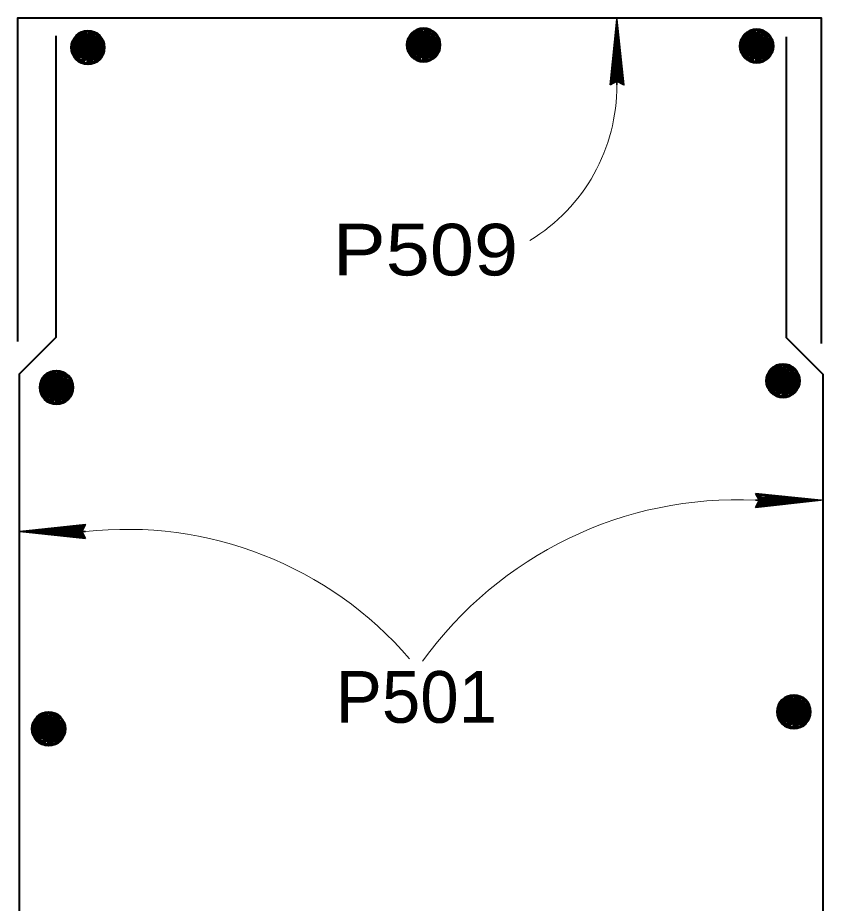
# Model space of a CAD drawing. Extents: x 6.34 to 9.53, y -1.46 to 0.53.
# Drawn here: x 7.8124 to 7.9424, y -0.5501 to -0.4073 of the extents above; entities that cross this region are included whole.
import ezdxf

# ---------------------------------------------------------------- set-up
doc = ezdxf.new("R2010")
doc.units = 0
doc.header["$LTSCALE"] = 0.0033
doc.layers.add('1', color=7, linetype='Continuous', lineweight=40)

msp = doc.modelspace()

# ---------------------------------------------------------------- linework, layer by layer
at = {"layer": '1', "lineweight": 35}
for p, q in [((7.909083, -0.418083), (7.909083, -0.4075)), ((7.908083, -0.417833), (7.909, -0.41)), ((7.908083, -0.417833), (7.909, -0.41)), ((7.908167, -0.417833), (7.909, -0.41)), ((7.90825, -0.417833), (7.909083, -0.41)), ((7.90825, -0.417833), (7.90925, -0.41)), ((7.90975, -0.417917), (7.909, -0.410583)), ((7.909917, -0.417833), (7.909083, -0.4105)), ((7.91, -0.417833), (7.90925, -0.4105)), ((7.910167, -0.417833), (7.909333, -0.4105)), ((7.93175, -0.484083), (7.939583, -0.485)), ((7.93175, -0.484083), (7.939583, -0.485)), ((7.93175, -0.484167), (7.939583, -0.485)), ((7.93175, -0.48425), (7.939583, -0.485083)), ((7.93175, -0.48425), (7.939583, -0.48525)), ((7.9315, -0.485083), (7.942083, -0.485083)), ((7.931667, -0.48575), (7.939, -0.485)), ((7.93175, -0.485917), (7.939083, -0.485083)), ((7.93175, -0.486), (7.939083, -0.48525)), ((7.93175, -0.486167), (7.939083, -0.485333)), ((7.823083, -0.491), (7.81525, -0.49)), ((7.823083, -0.489083), (7.81575, -0.489917)), ((7.823083, -0.48925), (7.81575, -0.49)), ((7.823083, -0.489333), (7.81575, -0.490167)), ((7.823167, -0.4895), (7.815833, -0.49025)), ((7.823333, -0.490167), (7.81275, -0.490167)), ((7.823083, -0.491), (7.81525, -0.490167)), ((7.823083, -0.491167), (7.81525, -0.49025)), ((7.823083, -0.491167), (7.81525, -0.49025)), ((7.823083, -0.491083), (7.81525, -0.49025))]:
    msp.add_line(p, q, dxfattribs=at)
at = {"layer": '1'}
for p, q in [((7.824, -0.411), (7.825333, -0.41)), ((7.826083, -0.410833), (7.824833, -0.409667)), ((7.87625, -0.40975), (7.880083, -0.410417)), ((7.878167, -0.410583), (7.8795, -0.409583)), ((7.88025, -0.410417), (7.879, -0.40925)), ((7.93, -0.409917), (7.933833, -0.410583)), ((7.931917, -0.41075), (7.93325, -0.40975)), ((7.934, -0.410583), (7.93275, -0.409417)), ((7.821667, -0.4105), (7.82625, -0.412667)), ((7.821917, -0.410917), (7.825833, -0.411667)), ((7.821917, -0.411083), (7.825833, -0.411833)), ((7.821917, -0.411333), (7.82575, -0.412083)), ((7.822, -0.4105), (7.825917, -0.411167)), ((7.822, -0.410667), (7.825917, -0.411417)), ((7.822083, -0.410167), (7.825917, -0.410833)), ((7.875833, -0.410083), (7.880417, -0.41225)), ((7.876, -0.411083), (7.879833, -0.41175)), ((7.876, -0.41125), (7.879833, -0.412)), ((7.876083, -0.4105), (7.88, -0.41125)), ((7.876083, -0.410667), (7.88, -0.411417)), ((7.876083, -0.410917), (7.879917, -0.411667)), ((7.876167, -0.410083), (7.880083, -0.41075)), ((7.876167, -0.41025), (7.880083, -0.411)), ((7.929583, -0.41025), (7.934167, -0.412417)), ((7.92975, -0.41125), (7.933583, -0.411917)), ((7.92975, -0.411417), (7.933583, -0.412167)), ((7.929833, -0.410667), (7.93375, -0.411417)), ((7.929833, -0.410833), (7.93375, -0.411583)), ((7.929833, -0.411083), (7.933667, -0.411833)), ((7.929917, -0.41025), (7.933833, -0.410917)), ((7.929917, -0.410417), (7.933833, -0.411167)), ((7.821583, -0.41275), (7.8255, -0.4135)), ((7.821667, -0.412333), (7.825583, -0.413083)), ((7.82175, -0.411917), (7.825583, -0.412667)), ((7.82175, -0.412083), (7.825583, -0.412833)), ((7.821833, -0.4115), (7.825667, -0.412167)), ((7.821833, -0.411667), (7.825667, -0.412417)), ((7.875667, -0.412833), (7.8795, -0.413583)), ((7.87575, -0.412333), (7.879667, -0.413083)), ((7.87575, -0.4125), (7.879583, -0.41325)), ((7.87575, -0.41275), (7.879583, -0.413417)), ((7.875833, -0.411917), (7.87975, -0.412667)), ((7.875917, -0.4115), (7.87975, -0.41225)), ((7.875917, -0.411667), (7.87975, -0.412417)), ((7.9295, -0.4125), (7.933417, -0.41325)), ((7.9295, -0.412667), (7.933333, -0.413417)), ((7.929583, -0.412083), (7.9335, -0.412833)), ((7.929667, -0.411667), (7.9335, -0.412417)), ((7.929667, -0.411833), (7.9335, -0.412583)), ((7.8215, -0.41325), (7.825333, -0.414)), ((7.8215, -0.413417), (7.825333, -0.414167)), ((7.821583, -0.412917), (7.825417, -0.413667)), ((7.821583, -0.413167), (7.825417, -0.413833)), ((7.825833, -0.413667), (7.822083, -0.414083)), ((7.875667, -0.413), (7.8795, -0.41375)), ((7.88, -0.41325), (7.87625, -0.413667)), ((7.929417, -0.413), (7.93325, -0.41375)), ((7.929417, -0.413167), (7.93325, -0.413917)), ((7.9295, -0.412917), (7.933333, -0.413583)), ((7.93375, -0.413417), (7.93, -0.413833)), ((7.933833, -0.46425), (7.938417, -0.466417)), ((7.934167, -0.46425), (7.938083, -0.464917)), ((7.93425, -0.463917), (7.938083, -0.464583)), ((7.936167, -0.46475), (7.9375, -0.46375)), ((7.93825, -0.464583), (7.937, -0.463417)), ((7.816583, -0.465333), (7.821167, -0.4675)), ((7.816833, -0.46575), (7.82075, -0.4665)), ((7.816917, -0.465333), (7.820833, -0.466)), ((7.816917, -0.4655), (7.820833, -0.46625)), ((7.817, -0.465), (7.820833, -0.465667)), ((7.818917, -0.465833), (7.82025, -0.464833)), ((7.821, -0.465667), (7.81975, -0.4645)), ((7.933917, -0.465667), (7.93775, -0.466417)), ((7.934, -0.46525), (7.937833, -0.465917)), ((7.934, -0.465417), (7.937833, -0.466167)), ((7.934083, -0.464667), (7.938, -0.465417)), ((7.934083, -0.464833), (7.938, -0.465583)), ((7.934083, -0.465083), (7.937917, -0.465833)), ((7.934167, -0.464417), (7.938083, -0.465167)), ((7.816583, -0.467167), (7.8205, -0.467917)), ((7.816667, -0.46675), (7.8205, -0.4675)), ((7.816667, -0.466917), (7.8205, -0.467667)), ((7.81675, -0.466333), (7.820583, -0.467)), ((7.81675, -0.4665), (7.820583, -0.46725)), ((7.816833, -0.465917), (7.82075, -0.466667)), ((7.816833, -0.466167), (7.820667, -0.466917)), ((7.933667, -0.467), (7.9375, -0.46775)), ((7.933667, -0.467167), (7.9375, -0.467917)), ((7.93375, -0.4665), (7.937667, -0.46725)), ((7.93375, -0.466667), (7.937583, -0.467417)), ((7.93375, -0.466917), (7.937583, -0.467583)), ((7.933833, -0.466083), (7.93775, -0.466833)), ((7.933917, -0.465833), (7.93775, -0.466583)), ((7.816417, -0.468083), (7.82025, -0.468833)), ((7.816417, -0.46825), (7.82025, -0.469)), ((7.8165, -0.467583), (7.820417, -0.468333)), ((7.8165, -0.46775), (7.820333, -0.4685)), ((7.8165, -0.468), (7.820333, -0.468667)), ((7.82075, -0.4685), (7.817, -0.468917)), ((7.938, -0.467417), (7.93425, -0.467833)), ((7.937917, -0.518167), (7.93925, -0.517167)), ((7.94, -0.518), (7.93875, -0.516833)), ((7.935583, -0.517667), (7.940167, -0.519833)), ((7.935833, -0.518083), (7.93975, -0.518833)), ((7.935833, -0.51825), (7.93975, -0.519)), ((7.935833, -0.5185), (7.939667, -0.51925)), ((7.935917, -0.517667), (7.939833, -0.518333)), ((7.935917, -0.517833), (7.939833, -0.518583)), ((7.936, -0.517333), (7.939833, -0.518)), ((7.817667, -0.520917), (7.819, -0.519917)), ((7.81975, -0.52075), (7.8185, -0.519583)), ((7.9355, -0.519917), (7.939417, -0.520667)), ((7.935583, -0.5195), (7.9395, -0.52025)), ((7.935667, -0.519083), (7.9395, -0.519833)), ((7.935667, -0.51925), (7.9395, -0.52)), ((7.93575, -0.518667), (7.939583, -0.519333)), ((7.93575, -0.518833), (7.939583, -0.519583)), ((7.815333, -0.520417), (7.819917, -0.522583)), ((7.8155, -0.521417), (7.819333, -0.522083)), ((7.815583, -0.520833), (7.8195, -0.521583)), ((7.815583, -0.521), (7.8195, -0.52175)), ((7.815583, -0.52125), (7.819417, -0.522)), ((7.815667, -0.520417), (7.819583, -0.521083)), ((7.815667, -0.520583), (7.819583, -0.521333)), ((7.81575, -0.520083), (7.819583, -0.52075)), ((7.935417, -0.520417), (7.93925, -0.521167)), ((7.935417, -0.520583), (7.93925, -0.521333)), ((7.9355, -0.520083), (7.939333, -0.520833)), ((7.9355, -0.520333), (7.939333, -0.521)), ((7.93975, -0.520833), (7.936, -0.52125)), ((7.81525, -0.522667), (7.819167, -0.523417)), ((7.81525, -0.522833), (7.819083, -0.523583)), ((7.815333, -0.52225), (7.81925, -0.523)), ((7.815417, -0.521833), (7.81925, -0.522583)), ((7.815417, -0.522), (7.81925, -0.52275)), ((7.8155, -0.521583), (7.819333, -0.522333)), ((7.815167, -0.523167), (7.819, -0.523917)), ((7.815167, -0.523333), (7.819, -0.524083)), ((7.81525, -0.523083), (7.819083, -0.52375)), ((7.8195, -0.523583), (7.81575, -0.524))]:
    msp.add_line(p, q, dxfattribs=at)
at = {"layer": '1', "lineweight": 60}
for p, q in [((7.821917, -0.4105), (7.82175, -0.413417)), ((7.822167, -0.4105), (7.821917, -0.413417)), ((7.822333, -0.4105), (7.822167, -0.4135)), ((7.8225, -0.4105), (7.82225, -0.4135)), ((7.822667, -0.4105), (7.8225, -0.4135)), ((7.822917, -0.4105), (7.82275, -0.4135)), ((7.823167, -0.4105), (7.822917, -0.4135)), ((7.82325, -0.410583), (7.823083, -0.4135)), ((7.823417, -0.410583), (7.82325, -0.4135)), ((7.823583, -0.410583), (7.823417, -0.4135)), ((7.823833, -0.410583), (7.823583, -0.4135)), ((7.824, -0.410583), (7.823833, -0.4135)), ((7.82425, -0.410667), (7.824, -0.413583)), ((7.8245, -0.410667), (7.82425, -0.413583)), ((7.824667, -0.410667), (7.8245, -0.413583)), ((7.82475, -0.410667), (7.824583, -0.413583)), ((7.824917, -0.410667), (7.82475, -0.413583)), ((7.825, -0.410667), (7.824833, -0.413583)), ((7.82525, -0.41075), (7.825, -0.413667)), ((7.825417, -0.41075), (7.82525, -0.413667)), ((7.825583, -0.41075), (7.825333, -0.413667)), ((7.82575, -0.41075), (7.825583, -0.413667)), ((7.826, -0.41075), (7.825833, -0.413667)), ((7.82625, -0.412667), (7.826083, -0.410833)), ((7.876083, -0.410083), (7.875917, -0.413)), ((7.876333, -0.410083), (7.876083, -0.413)), ((7.8765, -0.410083), (7.876333, -0.413083)), ((7.876667, -0.410083), (7.876417, -0.413083)), ((7.876833, -0.410083), (7.876667, -0.413083)), ((7.877083, -0.410083), (7.876917, -0.413083)), ((7.877333, -0.410083), (7.877083, -0.413083)), ((7.877417, -0.410167), (7.87725, -0.413083)), ((7.877583, -0.410167), (7.877417, -0.413083)), ((7.87775, -0.410167), (7.877583, -0.413083)), ((7.878, -0.410167), (7.87775, -0.413083)), ((7.878167, -0.410167), (7.878, -0.413083)), ((7.878417, -0.41025), (7.878167, -0.413167)), ((7.878667, -0.41025), (7.878417, -0.413167)), ((7.878833, -0.41025), (7.878667, -0.413167)), ((7.878917, -0.41025), (7.87875, -0.413167)), ((7.879083, -0.41025), (7.878917, -0.413167)), ((7.879167, -0.41025), (7.879, -0.413167)), ((7.879417, -0.410333), (7.879167, -0.41325)), ((7.879583, -0.410333), (7.879417, -0.41325)), ((7.87975, -0.410333), (7.8795, -0.41325)), ((7.879917, -0.410333), (7.87975, -0.41325)), ((7.880167, -0.410333), (7.88, -0.41325)), ((7.880417, -0.41225), (7.88025, -0.410417)), ((7.929833, -0.41025), (7.929667, -0.413167)), ((7.930083, -0.41025), (7.929833, -0.413167)), ((7.93025, -0.41025), (7.930083, -0.41325)), ((7.930417, -0.41025), (7.930167, -0.41325)), ((7.930583, -0.41025), (7.930417, -0.41325)), ((7.930833, -0.41025), (7.930667, -0.41325)), ((7.931083, -0.41025), (7.930833, -0.41325)), ((7.931167, -0.410333), (7.931, -0.41325)), ((7.931333, -0.410333), (7.931167, -0.41325)), ((7.9315, -0.410333), (7.931333, -0.41325)), ((7.93175, -0.410333), (7.9315, -0.41325)), ((7.931917, -0.410333), (7.93175, -0.41325)), ((7.932167, -0.410417), (7.931917, -0.413333)), ((7.932417, -0.410417), (7.932167, -0.413333)), ((7.932583, -0.410417), (7.932417, -0.413333)), ((7.932667, -0.410417), (7.9325, -0.413333)), ((7.932833, -0.410417), (7.932667, -0.413333)), ((7.932917, -0.410417), (7.93275, -0.413333)), ((7.933167, -0.4105), (7.932917, -0.413417)), ((7.933333, -0.4105), (7.933167, -0.413417)), ((7.9335, -0.4105), (7.93325, -0.413417)), ((7.933667, -0.4105), (7.9335, -0.413417)), ((7.933917, -0.4105), (7.93375, -0.413417)), ((7.934167, -0.412417), (7.934, -0.410583)), ((7.82625, -0.412667), (7.8215, -0.413417)), ((7.880417, -0.41225), (7.875667, -0.413)), ((7.934167, -0.412417), (7.929417, -0.413167)), ((7.934083, -0.46425), (7.933917, -0.467167)), ((7.934333, -0.46425), (7.934083, -0.467167)), ((7.9345, -0.46425), (7.934333, -0.46725)), ((7.934667, -0.46425), (7.934417, -0.46725)), ((7.934833, -0.46425), (7.934667, -0.46725)), ((7.935083, -0.46425), (7.934917, -0.46725)), ((7.935333, -0.46425), (7.935083, -0.46725)), ((7.935417, -0.464333), (7.93525, -0.46725)), ((7.935583, -0.464333), (7.935417, -0.46725)), ((7.93575, -0.464333), (7.935583, -0.46725)), ((7.936, -0.464333), (7.93575, -0.46725)), ((7.936167, -0.464333), (7.936, -0.46725)), ((7.816833, -0.465333), (7.816667, -0.46825)), ((7.817083, -0.465333), (7.816833, -0.46825)), ((7.81725, -0.465333), (7.817083, -0.468333)), ((7.817417, -0.465333), (7.817167, -0.468333)), ((7.817583, -0.465333), (7.817417, -0.468333)), ((7.817833, -0.465333), (7.817667, -0.468333)), ((7.818083, -0.465333), (7.817833, -0.468333)), ((7.818167, -0.465417), (7.818, -0.468333)), ((7.818333, -0.465417), (7.818167, -0.468333)), ((7.8185, -0.465417), (7.818333, -0.468333)), ((7.81875, -0.465417), (7.8185, -0.468333)), ((7.818917, -0.465417), (7.81875, -0.468333)), ((7.819167, -0.4655), (7.818917, -0.468417)), ((7.819417, -0.4655), (7.819167, -0.468417)), ((7.819583, -0.4655), (7.819417, -0.468417)), ((7.819667, -0.4655), (7.8195, -0.468417)), ((7.819833, -0.4655), (7.819667, -0.468417)), ((7.819917, -0.4655), (7.81975, -0.468417)), ((7.820167, -0.465583), (7.819917, -0.4685)), ((7.820333, -0.465583), (7.820167, -0.4685)), ((7.8205, -0.465583), (7.82025, -0.4685)), ((7.820667, -0.465583), (7.8205, -0.4685)), ((7.820917, -0.465583), (7.82075, -0.4685)), ((7.821167, -0.4675), (7.821, -0.465667)), ((7.936417, -0.464417), (7.936167, -0.467333)), ((7.936667, -0.464417), (7.936417, -0.467333)), ((7.936833, -0.464417), (7.936667, -0.467333)), ((7.936917, -0.464417), (7.93675, -0.467333)), ((7.937083, -0.464417), (7.936917, -0.467333)), ((7.937167, -0.464417), (7.937, -0.467333)), ((7.937417, -0.4645), (7.937167, -0.467417)), ((7.937583, -0.4645), (7.937417, -0.467417)), ((7.93775, -0.4645), (7.9375, -0.467417)), ((7.937917, -0.4645), (7.93775, -0.467417)), ((7.938167, -0.4645), (7.938, -0.467417)), ((7.938417, -0.466417), (7.93825, -0.464583)), ((7.938417, -0.466417), (7.933667, -0.467167)), ((7.821167, -0.4675), (7.816417, -0.46825)), ((7.935833, -0.517667), (7.935667, -0.520583)), ((7.936083, -0.517667), (7.935833, -0.520583)), ((7.93625, -0.517667), (7.936083, -0.520667)), ((7.936417, -0.517667), (7.936167, -0.520667)), ((7.936583, -0.517667), (7.936417, -0.520667)), ((7.936833, -0.517667), (7.936667, -0.520667)), ((7.937083, -0.517667), (7.936833, -0.520667)), ((7.937167, -0.51775), (7.937, -0.520667)), ((7.937333, -0.51775), (7.937167, -0.520667)), ((7.9375, -0.51775), (7.937333, -0.520667)), ((7.93775, -0.51775), (7.9375, -0.520667)), ((7.937917, -0.51775), (7.93775, -0.520667)), ((7.938167, -0.517833), (7.937917, -0.52075)), ((7.938417, -0.517833), (7.938167, -0.52075)), ((7.938583, -0.517833), (7.938417, -0.52075)), ((7.938667, -0.517833), (7.9385, -0.52075)), ((7.938833, -0.517833), (7.938667, -0.52075)), ((7.938917, -0.517833), (7.93875, -0.52075)), ((7.939167, -0.517917), (7.938917, -0.520833)), ((7.939333, -0.517917), (7.939167, -0.520833)), ((7.9395, -0.517917), (7.93925, -0.520833)), ((7.939667, -0.517917), (7.9395, -0.520833)), ((7.939917, -0.517917), (7.93975, -0.520833)), ((7.940167, -0.519833), (7.94, -0.518)), ((7.940167, -0.519833), (7.935417, -0.520583)), ((7.815583, -0.520417), (7.815417, -0.523333)), ((7.815833, -0.520417), (7.815583, -0.523333)), ((7.816, -0.520417), (7.815833, -0.523417)), ((7.816167, -0.520417), (7.815917, -0.523417)), ((7.816333, -0.520417), (7.816167, -0.523417)), ((7.816583, -0.520417), (7.816417, -0.523417)), ((7.816833, -0.520417), (7.816583, -0.523417)), ((7.816917, -0.5205), (7.81675, -0.523417)), ((7.817083, -0.5205), (7.816917, -0.523417)), ((7.81725, -0.5205), (7.817083, -0.523417)), ((7.8175, -0.5205), (7.81725, -0.523417)), ((7.817667, -0.5205), (7.8175, -0.523417)), ((7.817917, -0.520583), (7.817667, -0.5235)), ((7.818167, -0.520583), (7.817917, -0.5235)), ((7.818333, -0.520583), (7.818167, -0.5235)), ((7.818417, -0.520583), (7.81825, -0.5235)), ((7.818583, -0.520583), (7.818417, -0.5235)), ((7.818667, -0.520583), (7.8185, -0.5235)), ((7.818917, -0.520667), (7.818667, -0.523583)), ((7.819083, -0.520667), (7.818917, -0.523583)), ((7.81925, -0.520667), (7.819, -0.523583)), ((7.819417, -0.520667), (7.81925, -0.523583)), ((7.819667, -0.520667), (7.8195, -0.523583)), ((7.819917, -0.522583), (7.81975, -0.52075)), ((7.819917, -0.522583), (7.815167, -0.523333))]:
    msp.add_line(p, q, dxfattribs=at)
at = {"layer": '1'}
for points in [[(7.812417, -0.4595), (7.812417, -0.40725), (7.942083, -0.40725), (7.942083, -0.459833)], [(7.818583, -0.410167), (7.818583, -0.458833), (7.812667, -0.46475), (7.812667, -0.673083), (7.818583, -0.679), (7.818583, -0.711417)], [(7.9365, -0.708167), (7.9365, -0.679083), (7.942417, -0.673167), (7.942417, -0.464833), (7.9365, -0.458917), (7.9365, -0.410333)], [(7.8215, -0.413417), (7.823583, -0.414667), (7.825333, -0.414167), (7.82625, -0.412667)], [(7.875667, -0.413), (7.87775, -0.41425), (7.8795, -0.41375), (7.880417, -0.41225)], [(7.929417, -0.413167), (7.9315, -0.414417), (7.93325, -0.413917), (7.934167, -0.412417)], [(7.933667, -0.467167), (7.93575, -0.468417), (7.9375, -0.467917), (7.938417, -0.466417)], [(7.816417, -0.46825), (7.8185, -0.4695), (7.82025, -0.469), (7.821167, -0.4675)], [(7.935417, -0.520583), (7.9375, -0.521833), (7.93925, -0.521333), (7.940167, -0.519833)], [(7.815167, -0.523333), (7.81725, -0.524583), (7.819, -0.524083), (7.819917, -0.522583)]]:
    msp.add_lwpolyline(points, dxfattribs=at)
at = {"layer": '1', "lineweight": 35}
for points in [[(7.908, -0.418083), (7.909083, -0.4075), (7.91025, -0.418083), (7.909083, -0.4175)], [(7.909, -0.417333), (7.908917, -0.412667), (7.909, -0.412667), (7.909, -0.413583), (7.908917, -0.417333), (7.908833, -0.414333), (7.90875, -0.4175), (7.908667, -0.41525), (7.908583, -0.4175), (7.908833, -0.414), (7.909, -0.409333), (7.90925, -0.41025), (7.90925, -0.409), (7.90925, -0.417333), (7.909417, -0.414917), (7.909417, -0.4175), (7.909, -0.412167), (7.909667, -0.4175)], [(7.9315, -0.484), (7.942083, -0.485083), (7.9315, -0.48625), (7.932083, -0.485083)], [(7.93225, -0.485), (7.936917, -0.484917), (7.936917, -0.485), (7.936, -0.485), (7.93225, -0.484917), (7.93525, -0.484833), (7.932083, -0.48475), (7.934333, -0.484667), (7.932083, -0.484583), (7.935583, -0.484833), (7.94025, -0.485), (7.939333, -0.48525), (7.940583, -0.48525), (7.93225, -0.48525), (7.934667, -0.485417), (7.932083, -0.485417), (7.937417, -0.485), (7.932083, -0.485667)], [(7.823333, -0.49125), (7.81275, -0.490167), (7.823333, -0.489), (7.82275, -0.490167)], [(7.822583, -0.49025), (7.817917, -0.490333), (7.817917, -0.49025), (7.818833, -0.49025), (7.822583, -0.490333), (7.819583, -0.490417), (7.82275, -0.4905), (7.8205, -0.490583), (7.82275, -0.490667), (7.81925, -0.490417), (7.814583, -0.49025), (7.8155, -0.49), (7.81425, -0.49), (7.822583, -0.49), (7.820167, -0.489833), (7.82275, -0.489833), (7.817417, -0.49025), (7.82275, -0.489583)]]:
    msp.add_lwpolyline(points, close=True, dxfattribs=at)
at = {"layer": '1', "lineweight": 60}
for points in [[(7.825333, -0.414167), (7.825333, -0.41), (7.823667, -0.414667), (7.824167, -0.4095), (7.822083, -0.414083), (7.822833, -0.409583), (7.824417, -0.414583), (7.82125, -0.41125), (7.826083, -0.410833), (7.822833, -0.4145), (7.824833, -0.409667), (7.821667, -0.4105), (7.8215, -0.413417)], [(7.822083, -0.414083), (7.823583, -0.411833), (7.821417, -0.410917), (7.823417, -0.4095), (7.823583, -0.41175), (7.82525, -0.414083), (7.82125, -0.41175), (7.824, -0.411)], [(7.824833, -0.409667), (7.823583, -0.411833), (7.825833, -0.413667)], [(7.8795, -0.41375), (7.8795, -0.409583), (7.877833, -0.41425), (7.878333, -0.409083), (7.87625, -0.413667), (7.877, -0.409167), (7.878583, -0.414167), (7.875417, -0.410833), (7.88025, -0.410417), (7.877, -0.414083), (7.879, -0.40925), (7.875833, -0.410083), (7.875667, -0.413)], [(7.87625, -0.413667), (7.87775, -0.411417), (7.875583, -0.4105), (7.877583, -0.409083), (7.87775, -0.411333), (7.879417, -0.413667), (7.875417, -0.411333), (7.878167, -0.410583)], [(7.879, -0.40925), (7.87775, -0.411417), (7.88, -0.41325)], [(7.93325, -0.413917), (7.93325, -0.40975), (7.931583, -0.414417), (7.932083, -0.40925), (7.93, -0.413833), (7.93075, -0.409333), (7.932333, -0.414333), (7.929167, -0.411), (7.934, -0.410583), (7.93075, -0.41425), (7.93275, -0.409417), (7.929583, -0.41025), (7.929417, -0.413167)], [(7.93, -0.413833), (7.9315, -0.411583), (7.929333, -0.410667), (7.931333, -0.40925), (7.9315, -0.4115), (7.933167, -0.413833), (7.929167, -0.4115), (7.931917, -0.41075)], [(7.93275, -0.409417), (7.9315, -0.411583), (7.93375, -0.413417)], [(7.821083, -0.412167), (7.82625, -0.4115), (7.821667, -0.4105)], [(7.87525, -0.41175), (7.880417, -0.411083), (7.875833, -0.410083)], [(7.929, -0.411917), (7.934167, -0.41125), (7.929583, -0.41025)], [(7.82025, -0.469), (7.82025, -0.464833), (7.818583, -0.4695), (7.819083, -0.464333), (7.817, -0.468917), (7.81775, -0.464417), (7.819333, -0.469417), (7.816167, -0.466083), (7.821, -0.465667), (7.81775, -0.469333), (7.81975, -0.4645), (7.816583, -0.465333), (7.816417, -0.46825)], [(7.817, -0.468917), (7.8185, -0.466667), (7.816333, -0.46575), (7.818333, -0.464333), (7.8185, -0.466583), (7.820167, -0.468917), (7.816167, -0.466583), (7.818917, -0.465833)], [(7.93325, -0.465917), (7.938417, -0.46525), (7.933833, -0.46425)], [(7.9375, -0.467917), (7.9375, -0.46375), (7.935833, -0.468417), (7.936333, -0.46325), (7.93425, -0.467833), (7.935, -0.463333), (7.936583, -0.468333), (7.933417, -0.465), (7.93825, -0.464583), (7.935, -0.46825), (7.937, -0.463417), (7.933833, -0.46425), (7.933667, -0.467167)], [(7.93425, -0.467833), (7.93575, -0.465583), (7.933583, -0.464667), (7.935583, -0.46325), (7.93575, -0.4655), (7.937417, -0.467833), (7.933417, -0.4655), (7.936167, -0.46475)], [(7.937, -0.463417), (7.93575, -0.465583), (7.938, -0.467417)], [(7.816, -0.467), (7.821167, -0.466333), (7.816583, -0.465333)], [(7.81975, -0.4645), (7.8185, -0.466667), (7.82075, -0.4685)], [(7.93925, -0.521333), (7.93925, -0.517167), (7.937583, -0.521833), (7.938083, -0.516667), (7.936, -0.52125), (7.93675, -0.51675), (7.938333, -0.52175), (7.935167, -0.518417), (7.94, -0.518), (7.93675, -0.521667), (7.93875, -0.516833), (7.935583, -0.517667), (7.935417, -0.520583)], [(7.936, -0.52125), (7.9375, -0.519), (7.935333, -0.518083), (7.937333, -0.516667), (7.9375, -0.518917), (7.939167, -0.52125), (7.935167, -0.518917), (7.937917, -0.518167)], [(7.93875, -0.516833), (7.9375, -0.519), (7.93975, -0.520833)], [(7.935, -0.519333), (7.940167, -0.518667), (7.935583, -0.517667)], [(7.819, -0.524083), (7.819, -0.519917), (7.817333, -0.524583), (7.817833, -0.519417), (7.81575, -0.524), (7.8165, -0.5195), (7.818083, -0.5245), (7.814917, -0.521167), (7.81975, -0.52075), (7.8165, -0.524417), (7.8185, -0.519583), (7.815333, -0.520417), (7.815167, -0.523333)], [(7.81575, -0.524), (7.81725, -0.52175), (7.815083, -0.520833), (7.817083, -0.519417), (7.81725, -0.521667), (7.818917, -0.524), (7.814917, -0.521667), (7.817667, -0.520917)], [(7.8185, -0.519583), (7.81725, -0.52175), (7.8195, -0.523583)], [(7.81475, -0.522083), (7.819917, -0.521417), (7.815333, -0.520417)]]:
    msp.add_lwpolyline(points, dxfattribs=at)
at = {"layer": '1', "lineweight": 35}
for points in [[(7.909, -0.417333), (7.90825, -0.41775), (7.9085, -0.4175), (7.908833, -0.417333), (7.90875, -0.417083), (7.908417, -0.41725), (7.909167, -0.417417), (7.909667, -0.417583), (7.910083, -0.417833)], [(7.93225, -0.485), (7.931833, -0.48425), (7.932083, -0.4845), (7.93225, -0.484833), (7.9325, -0.48475), (7.932333, -0.484417), (7.932167, -0.485167), (7.932, -0.485667), (7.93175, -0.486083)], [(7.822583, -0.49025), (7.823, -0.491), (7.82275, -0.49075), (7.822583, -0.490417), (7.822333, -0.4905), (7.8225, -0.490833), (7.822667, -0.490083), (7.822833, -0.489583), (7.823083, -0.489167)]]:
    msp.add_lwpolyline(points, dxfattribs=at)
at = {"layer": '1', "lineweight": 60}
for centre in [(7.82375, -0.412067), (7.877917, -0.41165), (7.931667, -0.411817), (7.818667, -0.4669), (7.935917, -0.465817), (7.937667, -0.519233), (7.817417, -0.521983)]:
    msp.add_circle(centre, 0.00264, dxfattribs=at)
at = {"layer": '1', "lineweight": 13}
for centre, radius, start, end in [((7.880075, -0.418342), 0.029009, 301.15475, 0.51002), ((7.928556, -0.547556), 0.062542, 87.30189, 144.32616), ((7.830047, -0.550077), 0.060285, 40.82327, 96.39421)]:
    msp.add_arc(centre, radius, start, end, dxfattribs=at)

# ---------------------------------------------------------------- texts
at = {"layer": '1', "width": 1.15}
msp.add_text('P509', height=0.008334, dxfattribs=at).set_placement((7.86325, -0.448833))
at = {"layer": '1'}
msp.add_text('P501', height=0.008333, dxfattribs=at).set_placement((7.86375, -0.521))

doc.saveas('drawing.dxf')
